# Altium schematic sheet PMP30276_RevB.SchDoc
size 431 x 279 mm; Date: Not shown in title block; ApprovedBy: Not shown in title block; CheckedBy: Not shown in title block; Author: Not shown in title block; CompanyName: Not shown in title block; Engineer: Not shown in title block; Organization: Not shown in title block; Address1: Not shown in title block; Address2: Not shown in title block; Address3: Not shown in title block; Address4: Not shown in title block; DocumentNumber: 1; Revision: Use project parameter SCH_Rev; SheetNumber: 1; SheetTotal: 1; PageSetup: Record=PageOptions¦CenterHorizontal=True¦CenterVertical=True¦PrintScale=1.00¦XCorrection=1.00¦YCorrection=1.00¦PrintKind=0¦BorderSize=5000000¦LeftOffset=0¦BottomOffset=0¦Orientation=2¦PaperLength=1000¦PaperWidth=1000¦Scale=100¦PaperSource=15¦PrintQuality=600¦MediaType=1¦DitherType=10¦PaperKind=Letter¦PrintScaleMode=1
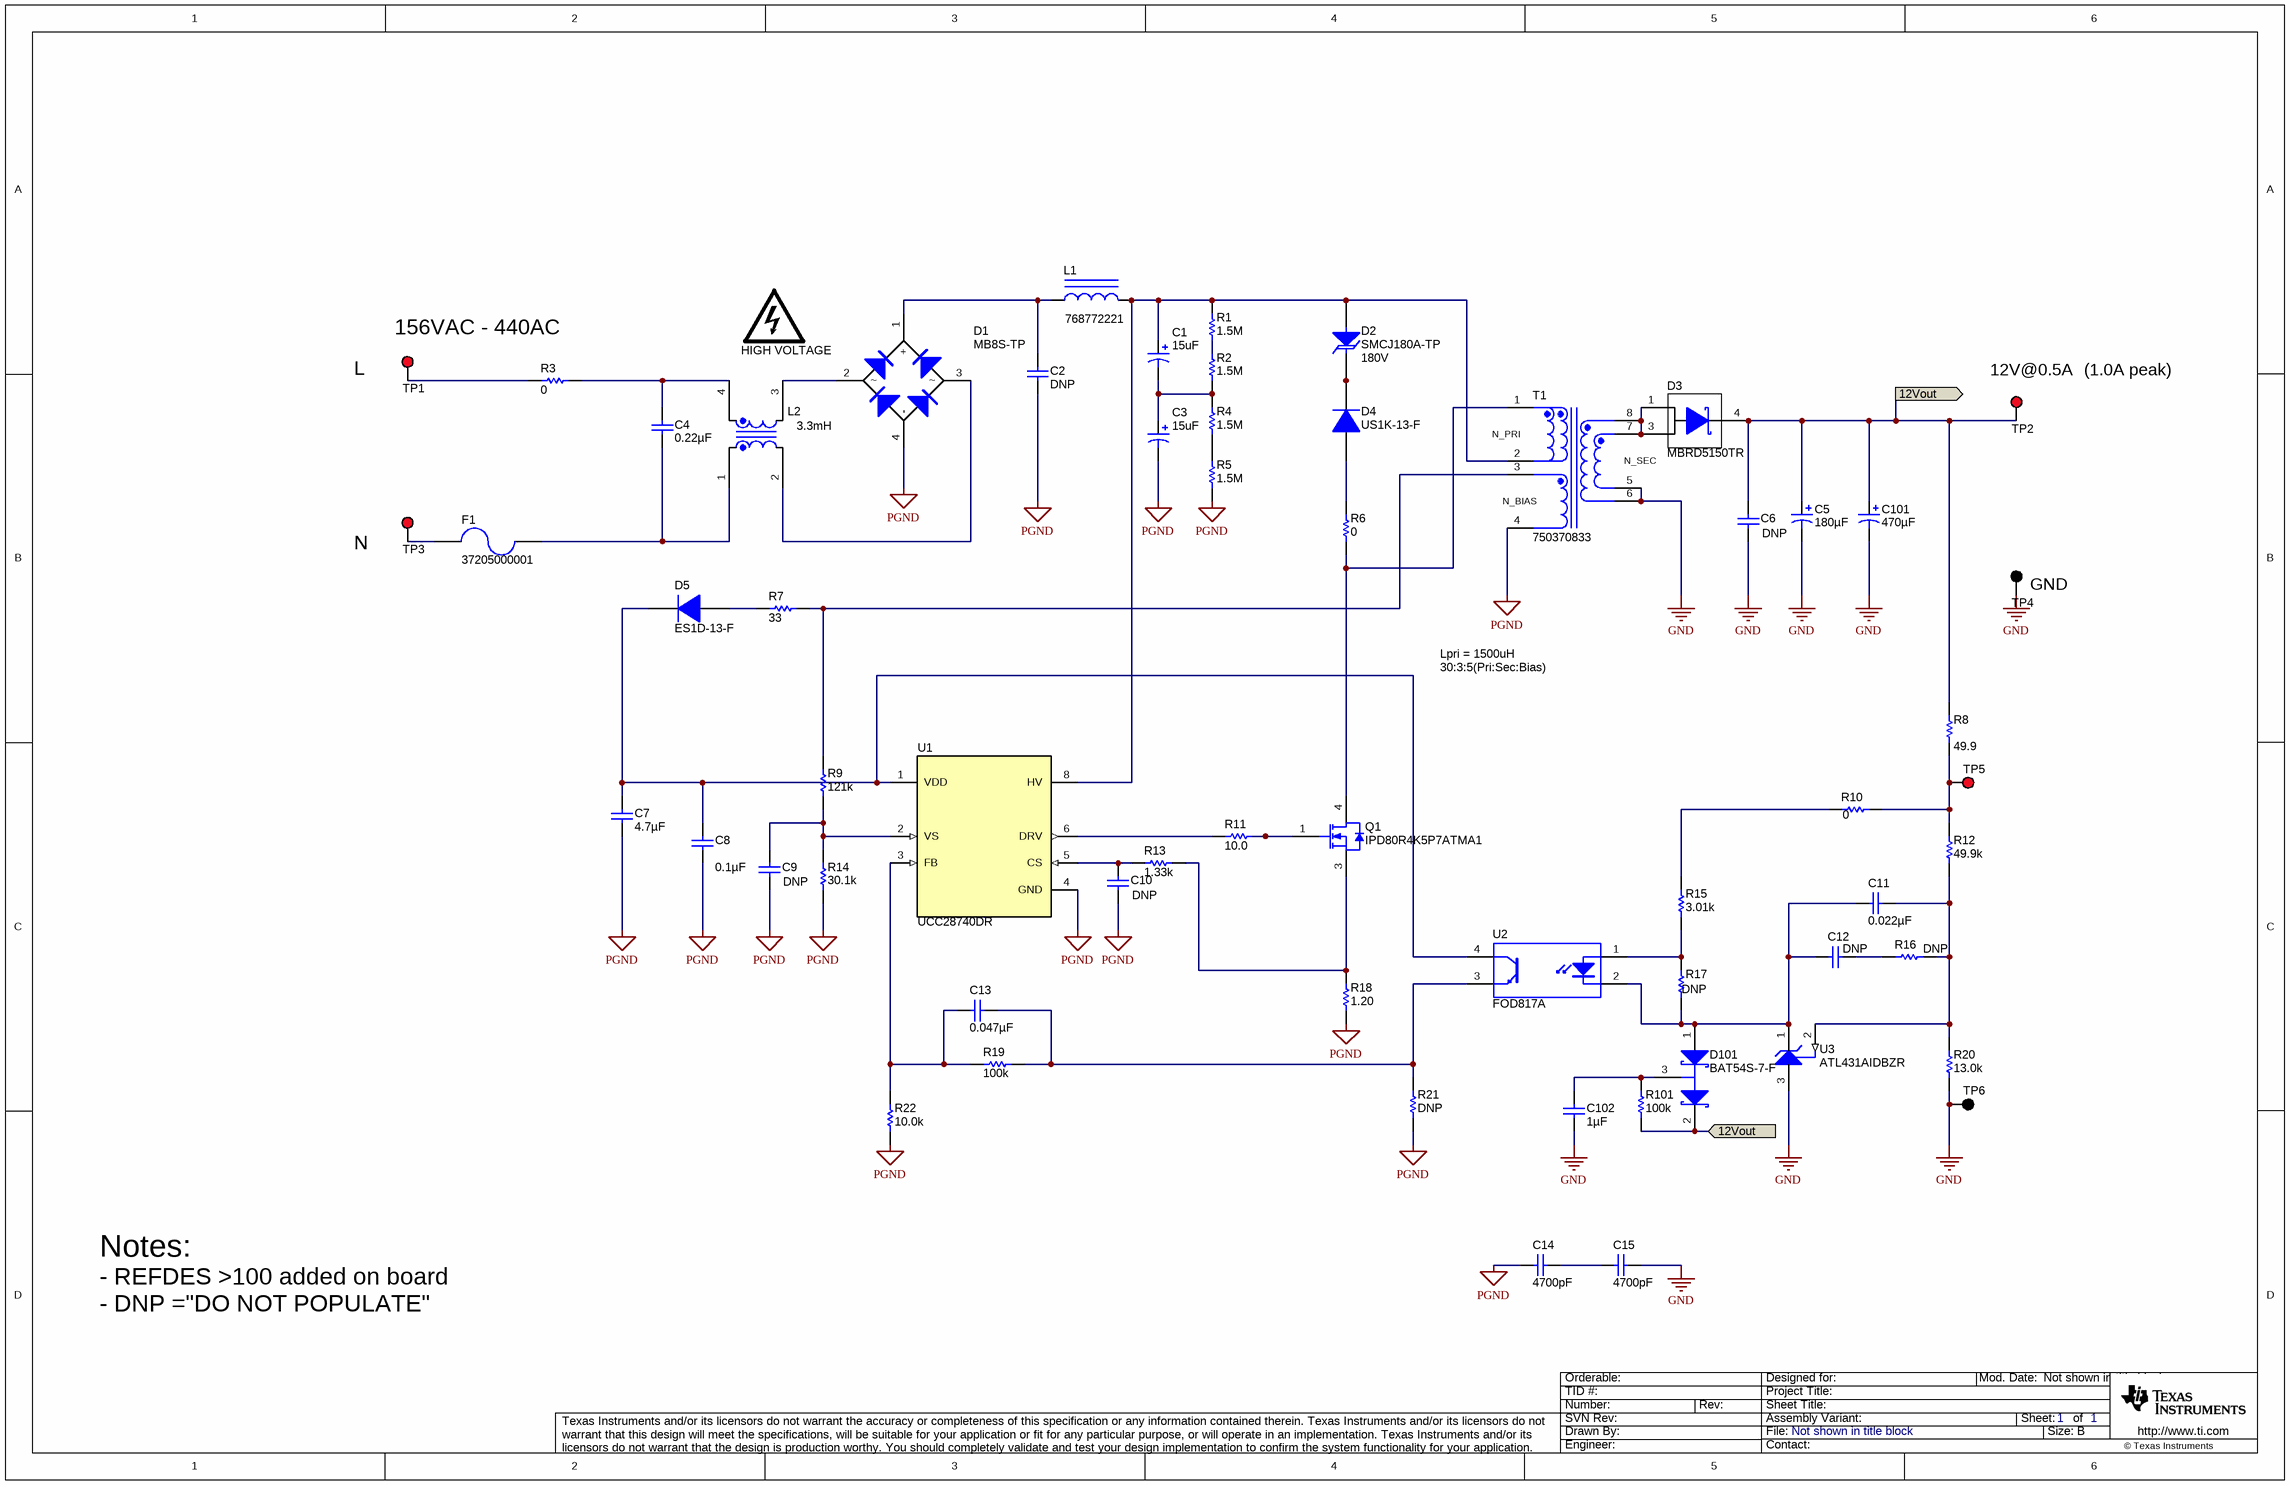
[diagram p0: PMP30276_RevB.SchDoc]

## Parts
C1  value 15uF  [CAPPR5-10x20]  (hidden comment: EEU-EE2V150)
C2  DNP  [B32913_2650x1050x1850]
C3  value 15uF  [CAPPR5-10x20]  (hidden comment: EEU-EE2V150)
C4  ValueDisplayed: 0.22µF  [B32913_2650x1050x1850]  (hidden comment: R474N322050A1K)
C5  ValueDisplayed: 180µF  [CAPSMT_62_F61]  (hidden comment: 16SVPF180M)
C6  value DNP  [1210]  (hidden comment: Used in BOM report)
C7  ValueDisplayed: 4.7µF  [1206_180]  (hidden comment: C3216X7R1H475K160AC)
C8  ValueDisplayed: 0.1µF  [0603]  (hidden comment: 06035C104KAT2A)
C9  value DNP  [0603_HV]  (hidden comment: Used in BOM report)
C10  value DNP  [0603]  (hidden comment: Used in BOM report)
C11  ValueDisplayed: 0.022µF  [0603]  (hidden comment: C0603C223K5RACTU)
C12  value DNP  [0805]  (hidden comment: Used in BOM report)
C13  ValueDisplayed: 0.047µF  [0603]  (hidden comment: C1608X7R1H473K080AA)
C14  ValueDisplayed: 4700pF  [KY_1000x500x1300]  (hidden comment: DE2E3KY472MB3BM02F)
C15  ValueDisplayed: 4700pF  [KY_1000x500x1300]  (hidden comment: DE2E3KY472MB3BM02F)
C101  ValueDisplayed: 470µF  [SM_RADIAL_10BMM]  (hidden comment: EEHZK1E471P)
C102  ValueDisplayed: 1µF  [0805_HV]  (hidden comment: GRM21BR71E105KA99L)
D1  MB8S-TP  [MBS-1]
D2  SMCJ180A-TP  value 180V  [SMC_265]
D3  MBRD5150TR  [DPAK]
D4  US1K-13-F  [SMA]
D5  ES1D-13-F  [SMA]
D101  BAT54S-7-F  [SOT-23]
F1  37205000001  [FUSE_372]
HIGH_VOLTAGE  DANGER HIGH VOLTAGE  [IEC_HighVoltage_Small]  (value not drawn)  (no BOM)
L1  768772221  [WE-TI_8095]
L2  value 3.3mH  [WE-CMB_Type_S]  (hidden comment: 744822233)
Q1  IPD80R4K5P7ATMA1  [DPAK]
R1  ValueDisplayed: 1.5M  [0805_HV]  (hidden comment: CRCW08051M50JNEA)
R2  ValueDisplayed: 1.5M  [0805_HV]  (hidden comment: CRCW08051M50JNEA)
R3  ValueDisplayed: 0  [1206]  (hidden comment: CRCW12060000Z0EA)
R4  ValueDisplayed: 1.5M  [0805_HV]  (hidden comment: CRCW08051M50JNEA)
R5  ValueDisplayed: 1.5M  [0805_HV]  (hidden comment: CRCW08051M50JNEA)
R6  ValueDisplayed: 0  [2512]  (hidden comment: CRCW25120000Z0EG)
R7  ValueDisplayed: 33  [0805_HV]  (hidden comment: CRCW080533R0JNEA)
R8  ValueDisplayed: 49.9  [0603]  (hidden comment: CRCW060349R9FKEA)
R9  ValueDisplayed: 121k  [0603]  (hidden comment: CRCW0603121KFKEA)
R10  ValueDisplayed: 0  [0603]  (hidden comment: CRCW06030000Z0EA)
R11  ValueDisplayed: 10.0  [0805_HV]  (hidden comment: RC0805FR-0710RL)
R12  ValueDisplayed: 49.9k  [0603]  (hidden comment: CRCW060349K9FKEA)
R13  ValueDisplayed: 1.33k  [0603]  (hidden comment: CRCW06031K33FKEA)
R14  ValueDisplayed: 30.1k  [0603]  (hidden comment: CRCW060330K1FKEA)
R15  ValueDisplayed: 3.01k  [0603]  (hidden comment: CRCW06033K01FKEA)
R16  value DNP  [0603]  (hidden comment: Used in BOM report)
R17  value DNP  [0603]  (hidden comment: Used in BOM report)
R18  ValueDisplayed: 1.20  [0805_HV]  (hidden comment: ERJ-6RQF1R2V)
R19  ValueDisplayed: 100k  [0603]  (hidden comment: CRCW0603100KFKEA)
R20  ValueDisplayed: 13.0k  [0603]  (hidden comment: CRCW060313K0FKEA)
R21  value DNP  [0603]  (hidden comment: Used in BOM report)
R22  ValueDisplayed: 10.0k  [0603]  (hidden comment: CRCW060310K0FKEA)
R101  ValueDisplayed: 100k  [0805_HV]  (hidden comment: CRCW0805100KFKEA)
T1  750370833  [Wurth_750370833]
TP1  5000  [Keystone5000]  (value not drawn)
TP2  5000  [Keystone5000]  (value not drawn)
TP3  5000  [Keystone5000]  (value not drawn)
TP4  5001  [Keystone5001]  (value not drawn)
TP5  5000  [Keystone5000]  (value not drawn)
TP6  5001  [Keystone5001]  (value not drawn)
U1  UCC28740DR  [D0007A_N]
U2  FOD817A  [DIP-4]
U3  ATL431AIDBZR  [DBZ0003A_N]

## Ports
12Vout (in), 12Vout (out)

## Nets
GND: C5.2(-) C6.2 C15.1 C101.2(-) C102.2 R20.1 T1.5 T1.6 TP4.1 TP6.1 U3.3(ANODE)
PGND: C2.2 C3.2(-) C7.2 C8.2 C9.2 C10.2 C14.2 D1.4(-) R5.1 R14.1 R18.1 R21.2 R22.1 T1.4 U1.4(GND)
12Vout: C5.1(+) C6.1 C101.1(+) D3.4(K) D101.2(K) R8.2 R101.1 TP2.1 ; port 12Vout
NetC1_1: C1.1(+) D2.2(A) L1.2 R1.2 T1.2 U1.8(HV)
NetC1_2: C1.2(-) C3.1(+) R2.1 R4.2
NetC2_1: C2.1 D1.1(+) L1.1
NetC4_1: C4.1 L2.4 R3.2
NetC4_2: C4.2 F1.1 L2.1
NetC7_1: C7.1 C8.1 D5.1(K) U1.1(VDD) U2.4(C)
NetC9_1: C9.1 R9.1 R14.2 U1.2(VS)
NetC10_1: C10.1 R13.1 U1.5(CS)
NetC11_1: C11.1 R12.1 R16.1 R20.2 U3.2(REF)
NetC11_2: C11.2 C12.1 D101.1(A) R17.1 U2.2(K) U3.1(CATHODE)
NetC12_2: C12.2 R16.2
NetC13_1: C13.1 R19.2 R21.1 U2.3(E)
NetC13_2: C13.2 R19.1 R22.2 U1.3(FB)
NetC14_1: C14.1 C15.2
NetC102_1: C102.1 D101.3(C) R101.2
NetD1_2: D1.2 L2.3
NetD1_3: D1.3 L2.2
NetD2_1: D2.1(K) D4.1(K)
NetD3_1: D3.1(A) D3.3(A) T1.7 T1.8
NetD4_2: D4.2(A) R6.2
NetD5_2: D5.2(A) R7.1
NetF1_2: F1.2 TP3.1
NetQ1_1: Q1.1(G) R11.2
NetQ1_3: Q1.3(S) R13.2 R18.2
NetQ1_4: Q1.4(D) R6.1 T1.1
NetR1_1: R1.1 R2.2
NetR3_1: R3.1 TP1.1
NetR4_1: R4.1 R5.2
NetR7_2: R7.2 R9.2 T1.3
NetR8_1: R8.1 R10.2 R12.2 TP5.1
NetR10_1: R10.1 R15.2
NetR11_1: R11.1 U1.6(DRV)
NetR15_1: R15.1 R17.2 U2.1(A)

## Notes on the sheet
- 156VAC - 440AC
- (near TP1) L
- (near T1) N_PRI
- (near TP2) 12V@0.5A
- (1.0A peak)
- (near T1) N_BIAS
- N_SEC
- (near TP3) N
- (near TP4) GND
- 30:3:5(Pri:Sec:Bias)
- Lpri = 1500uH
- Notes:
- - REFDES >100 added on board
- - DNP ="DO NOT POPULATE"

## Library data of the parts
C1 C3 = Capacitor_Polarized: CAP, [Technology], 15uF, 350V, +/-xx%, xxOhm ESR, [MountType]; Manufacturer: Used in BOM report; Polarized: Y; U/M: EA; Dielectric Material: Aluminium; Tolerance_%: 20%; Ripple Current: 480mA; Life (Hours): 8000Hour; Leakage Current: 325uA; Dissipation Factor: 0.2%; Lead Diameter: 0.6mm
C2 = B32913B5224K000: CAP, Film; Manufacturer: TDK; Polarized: N; CompType: Capacitor; U/M: EA; Cap_F: 0.00000022; Tolerance_%: 10; VDC_V: 1000; Value2: 440VAC; TaMin_C: -40; TaMax_C: 110; Cap_Case: 26.5x10.5x18.5mm; SizeAreaWB_mm2: 356.25; SizeArea_mm2: 278.25; SizeX_mm: 26.5; SizeY_mm: 10.5; SizeZ_mm: 18.5; AEC Category: Q200; Green_Lifecycle: Not Set; Green_REACh: Incomplete; Dielectric Material: PP; Voltage Rating (AC): 440V; Voltage Rating (DC): 1kV
C4 = B32913B5224K000: CAP, Film, 0.22 µF, 440VAC,+/- 10%, TH; Manufacturer: TDK; Polarized: N; CompType: Capacitor; Value: 0.22uF; U/M: EA; Cap_F: 0.00000022; Tolerance_%: 10; VDC_V: 1000; TaMin_C: -40; TaMax_C: 110; Cap_Case: 26.5x10.5x18.5mm; SizeAreaWB_mm2: 356.25; SizeArea_mm2: 278.25; SizeX_mm: 26.5; SizeY_mm: 10.5; SizeZ_mm: 18.5; AEC Category: Q200; Green_Lifecycle: Not Set; Green_REACh: Incomplete; Dielectric Material: PP; Voltage Rating (AC): 440V; Voltage Rating (DC): 1kV
C5 = 16SVPF180M: CAP, Aluminum Polymer, 180 µF, 16 V,+/- 20%, 0.022 ohm, F61 SMD; Manufacturer: Panasonic; Polarized: Y; CompType: Capacitor; Value: 180uF; U/M: EA; Cap_F: 0.00018; Tolerance_%: 20; VDC_V: 16; Value2: 16V; ESR_ohm: 0.022; IRMS_A: 3.3; TaMin_C: -55; TaMax_C: 105; SizeAreaWB_mm2: 73.96; SizeArea_mm2: 43.56; SizeX_mm: 6.6; SizeZ_mm: 5.8; AEC Category: Q200; Green_Lifecycle: Not Set; Green_REACh: Incomplete
C6 C9 C10 C12 = Capacitor: CAP, CERM, xxxF, xxV, [TempCo], xx%, [PackageReference]; Polarized: N; U/M: EA
C7 = C3216X7R1H475K160AC: CAP, CERM, 4.7 µF, 50 V,+/- 10%, X7R, 1206; Manufacturer: TDK; Polarized: N; CompType: Capacitor; Value: 4.7uF; U/M: EA; Cap_F: 0.0000047; Tolerance_%: 10; ESR_ohm: 0.003158; Value1: 0.003158 ohm; VDC_V: 50; Value2: 50V; IRMS_A: 4.08379; TaMin_C: -55; TaMax_C: 125; Cap_Case: 1206; SizeArea_mm2: 5.12; SizeAreaWB_mm2: 10.92; SizeX_mm: 3.2; SizeY_mm: 1.6; SizeZ_mm: 1.8; AEC Category: Q200
C8 = 06035C104KAT2A: CAP, CERM, 0.1 µF, 50 V, +/- 10%, X7R, 0603; Manufacturer: AVX; Polarized: N; CompType: Capacitor; Value: 0.1uF; U/M: EA; Cap_F: 0.0000001; Tolerance_%: 10; Value1: Unknown; VDC_V: 50; Value2: 50V; TaMin_C: -55; TaMax_C: 125; SizeArea_mm2: 1.28; SizeAreaWB_mm2: 4.68; SizeX_mm: 1.6; SizeY_mm: 0.8; SizeZ_mm: 1; AEC Category: Q200
C11 = C0603C223K5RACTU: CAP, CERM, 0.022 µF, 50 V,+/- 10%, X7R, 0603; Manufacturer: Kemet; Polarized: N; CompType: Capacitor; Value: 0.022uF; U/M: EA; Cap_F: 0.000000022; Tolerance_%: 10; VDC_V: 50; Value2: 50V; TaMin_C: -55; TaMax_C: 125; SizeArea_mm2: 1.28; SizeAreaWB_mm2: 4.68; SizeX_mm: 1.6; SizeY_mm: 0.8; SizeZ_mm: 1; AEC Category: Q200; Green_Lifecycle: Active; Green_REACh: Passed
C13 = C1608X7R1H473K080AA: CAP, CERM, 0.047 µF, 50 V,+/- 10%, X7R, 0603; Manufacturer: TDK; Polarized: N; CompType: Capacitor; Value: 0.047uF; U/M: EA; Cap_F: 0.000000047; Tolerance_%: 10; ESR_ohm: 0.049007; Value1: 0.049007 ohm; VDC_V: 50; Value2: 50V; IRMS_A: 0.767528; TaMin_C: -55; TaMax_C: 125; SizeArea_mm2: 1.28; SizeAreaWB_mm2: 4.68; SizeX_mm: 1.6; SizeY_mm: 0.8; SizeZ_mm: 1; AEC Category: Q200; Green_Lifecycle: NRND; Green_REACh: Passed
C14 C15 = DE2E3KY472MB3BM02F: CAP, CERM, 4700 pF, X1 250 VAC/Y2 300 VAC, +/- 20%, E, 10x5x13mm; Manufacturer: MuRata; Polarized: N; CompType: Capacitor; Value: 4700pF; U/M: EA; Cap_F: 0.0000000047; Tolerance_%: 20; TaMin_C: -40; TaMax_C: 125; SizeArea_mm2: 50; SizeAreaWB_mm2: 84; SizeX_mm: 10; SizeY_mm: 5; SizeZ_mm: 13; AEC Category: Q200; AC_Safety: X1Y2; VAC_X: 250; VAC_Y: 300
C101 = EEHZC1E331P: CAP, Polymer Hybrid, 470 µF, 25 V,; Manufacturer: Panasonic; Polarized: Y; CompType: Capacitor; Value: 470uF; U/M: EA; Cap_F: 0.00033; Tolerance_%: 20; VDC_V: 25; Value2: 25V; IRMS_A: 2; TaMin_C: -55; TaMax_C: 125; SizeAreaWB_mm2: 159.9; SizeArea_mm2: 113.3; SizeX_mm: 11; SizeY_mm: 10.3; SizeZ_mm: 10.2; AEC Category: Q200
C102 = GRM21BR71E105KA99L: CAP, CERM, 1 µF, 25 V,+/- 10%, X7R, 0805; Manufacturer: MuRata; Polarized: N; CompType: Capacitor; Value: 1uF; U/M: EA; Cap_F: 0.000001; Tolerance_%: 10; VDC_V: 25; Value2: 25V; TaMin_C: -55; TaMax_C: 125; Cap_Case: 0805; SizeArea_mm2: 2.5; SizeAreaWB_mm2: 6.75; SizeX_mm: 2; SizeY_mm: 1.25; SizeZ_mm: 1.45; AEC Category: Q200; Green_Lifecycle: Active; Green_REACh: Passed
D1 = MB8S-TP: Diode, Switching-Bridge, 800 V, 0.5 A, TO269AA; Manufacturer: Micro Commercial Components; U/M: EA; Vf_V: 1; Value: 800V; Value1: 0.5A; Value2: 1V; Io_A: 0.5; Vr_V: 800; TJmax_C: 150; SizeAreaWB_mm2: 58.725; SizeArea_mm2: 31.825; SizeX_mm: 6.7; SizeY_mm: 4.75; SizeZ_mm: 2.7; AEC Category: Q101; Green_Lifecycle: Not Set; Green_REACh: Incomplete
D2 = SMCJ160A-TP: Diode, TVS, Uni, 180 V,; Manufacturer: Micro Commercial Components; U/M: EA; Vr_V: 160; Value1: W; SizeAreaWB_mm2: 78.5757; SizeArea_mm2: 46.8857; SizeX_mm: 7.94; SizeY_mm: 5.905; SizeZ_mm: 2.62; AEC Category: Q101; AEC Qualified: N
D3 = DIODE_SCHOTTKY_A13C4: Diode, Schottky, 150V, 5A, [PackageReference]; Manufacturer: SMC Diode Solutions; U/M: EA
D4 = US1K-13-F: Diode, Fast Rectifier, 800 V, 1 A, SMA; Manufacturer: Diodes Inc.; U/M: EA; Vf_V: 1.7; Value: 800V; Value1: 1A; Value2: 1.7V; Io_A: 1; Vr_V: 800; TJmax_C: 150; SizeAreaWB_mm2: 37.3428; SizeArea_mm2: 16.3228; SizeX_mm: 5.59; SizeY_mm: 2.92; SizeZ_mm: 2.87; AEC Category: Q101; Green_Lifecycle: Not Set; Green_REACh: Incomplete
D5 = ES1D-13-F: Diode, Ultrafast, 200 V, 1 A, SMA; Manufacturer: Diodes Inc.; U/M: EA; Vf_V: 0.92; Value: 200V; Value1: 1A; Value2: 0.92V; Io_A: 1; Vr_V: 200; TJmax_C: 150; RJC_CperW: 25; SizeAreaWB_mm2: 37.3428; SizeArea_mm2: 16.3228; SizeX_mm: 5.59; SizeY_mm: 2.92; SizeZ_mm: 2.87; AEC Category: Q101; Green_Lifecycle: Active; Green_REACh: Passed
D101 = BAT54S-7-F: Diode, Schottky, 30 V, 0.2 A, SOT-23; Manufacturer: Diodes Inc.; U/M: EA; Vf_V: 0.65; Value: 30V; Value1: 0.2A; Value2: 0.65V; Io_A: 0.2; Vr_V: 30; TJmax_C: 125; SizeAreaWB_mm2: 14; SizeArea_mm2: 7.5; SizeX_mm: 2.5; SizeY_mm: 3; SizeZ_mm: 1.1; AEC Category: Q101; Green_Lifecycle: Active; Green_REACh: Passed
F1 = 37205000001: Fuse, 0.5 A, 250VAC/VDC, TH; Manufacturer: Littelfuse; VDC_V: 250; Irating_A: 0.5
HIGH_VOLTAGE = IEC_HighVoltage: IEC 61010-1 High Voltage Warning; SymbolCreator: a0412235
L1 = 768772681: Inductor, Unshielded Drum Core, Powdered Iron, 220 µH,; Manufacturer: Wurth Elektronik; Value: 220uH; ValueDisplayed: 220µH; Ind_H: 680.0E-6; Imax_A: 0.76; Isat: 0.76A @ 10% inductance drop; DCR_ohm: 1.68; Value1: 1.68 ohm; Value2: 0.76A; SizeAreaWB_mm2: 96.04; SizeArea_mm2: 60.84; SizeX_mm: 7.8; SizeZ_mm: 10; AEC Category: Q200; Green_Lifecycle: Active; Green_REACh: Passed; Tolerance_%: 10%; Current Rating: 900mA; Saturation Current: 1.3A; Self Resonant Frequency: 3.7MHz; Test Frequency: 100KHz
L2 = 744822110: Coupled inductor, 3300uH, 1.5 A; Manufacturer: Wurth Elektronik; SymbolCreator: a0412235; Ind_H: 10.0E-3; DCR_ohm: 0.36; AEC Category: Q200
Q1 = IPD80R1K0CEBTMA1: MOSFET, N-CH, 800 V, DPAK; Manufacturer: Infineon Technologies; Alternate Manufacturer: None; U/M: EA; ChType: N; Value: 800V; VdsMax_V: 800; Value1: ? ohm; QgTyp_nC: 31; Vgs_V: 20; IdsMax_A: 5.7; SizeAreaWB_mm2: 101.7114; SizeArea_mm2: 64.8114; SizeX_mm: 9.91; SizeY_mm: 6.54; SizeZ_mm: 2.29; AEC Category: Q101; Green_Lifecycle: Not Set; Green_REACh: Incomplete; Continuous Drain Current (ID): 1.5A; Max Power Dissipation: 13W
R1 R2 R4 R5 = CRCW08051M50JNEA: RES, 1.5 M, 5%, 0.125 W, 0805; Manufacturer: Vishay-Dale; CompType: Resistor; Value: 1.5Meg; Res_ohm: 1500000; Value_Code: 1M50; Tolerance_%: 5; Power_W: 0.125; Value2: 0.125W; VDC_V: 150; TempCo: 200 ppm/C; SizeArea_mm2: 2.5; SizeX_mm: 2; SizeY_mm: 1.25; SizeZ_mm: 1.45; EIA_Code: E24; U/M: EA; AEC Category: Q200; Green_Lifecycle: Active; Green_REACh: Passed
R3 = CRCW12060000Z0EA: RES, 0, 5%, 0.25 W, 1206; Manufacturer: Vishay-Dale; CompType: Resistor; Value: 0; Value_Code: 0000; Tolerance_%: 5; Power_W: 0.25; Value2: 0.25W; VDC_V: 200; TempCo: 200 ppm/C; SizeArea_mm2: 5.12; SizeX_mm: 3.2; SizeY_mm: 1.6; SizeZ_mm: 1.35; EIA_Code: E24; U/M: EA; AEC Category: Q200; Green_Lifecycle: Active; Green_REACh: Passed
R6 = CRCW25120000Z0EG: RES, 0, 5%, 1 W, AEC-Q200 Grade 0, 2512; Manufacturer: Vishay-Dale; CompType: Resistor; Value: 0; Value_Code: 0000; Tolerance_%: 5; Power_W: 1; Value2: 1W; TempCo: ppm/C; SizeArea_mm2: 20.16; SizeX_mm: 6.3; SizeY_mm: 3.2; SizeZ_mm: 0.71; EIA_Code: E24; U/M: EA; AEC Category: Q200; AEC Qualified: Y
R7 = CRCW080533R0JNEA: RES, 33, 5%, 0.125 W, 0805; Manufacturer: Vishay-Dale; CompType: Resistor; Value: 33; Value_Code: 33R0; Tolerance_%: 5; Power_W: 0.125; Value2: 0.125W; VDC_V: 150; TempCo: 200 ppm/C; SizeArea_mm2: 2.5; SizeX_mm: 2; SizeY_mm: 1.25; SizeZ_mm: 1.45; EIA_Code: E24; U/M: EA; AEC Category: Q200
R8 = CRCW060349R9FKEA: RES, 49.9, 1%, 0.1 W, 0603; Manufacturer: Vishay-Dale; CompType: Resistor; Value: 49.9; Value_Code: 49R9; Tolerance_%: 1; Power_W: 0.1; Value2: 0.1W; VDC_V: 75; TempCo: 100 ppm/C; SizeArea_mm2: 1.28; SizeX_mm: 1.6; SizeY_mm: 0.8; EIA_Code: E96; U/M: EA; AEC Category: Q200
R9 = CRCW0603121KFKEA: RES, 121 k, 1%, 0.1 W, 0603; Manufacturer: Vishay-Dale; CompType: Resistor; Value: 121k; Res_ohm: 121000; Tolerance_%: 1; Power_W: 0.1; Value2: 0.1W; VDC_V: 75; TempCo: 100 ppm/C; SizeArea_mm2: 1.28; SizeX_mm: 1.6; SizeY_mm: 0.8; EIA_Code: E96; U/M: EA; AEC Category: Q200; Green_Lifecycle: Active; Green_REACh: Passed
R10 = CRCW06030000Z0EA: RES, 0, 5%, 0.1 W, 0603; Manufacturer: Vishay-Dale; CompType: Resistor; Value: 0; Value_Code: 0000; Tolerance_%: 5; Power_W: 0.1; Value2: 0.1W; VDC_V: 75; TempCo: 200 ppm/C; SizeArea_mm2: 1.28; SizeX_mm: 1.6; SizeY_mm: 0.8; SizeZ_mm: 1; EIA_Code: E24; U/M: EA; AEC Category: Q200
R11 = RC0805FR-0710RL: RES, 10.0, 1%, 0.125 W, 0805; Manufacturer: Yageo America; CompType: Resistor; Value: 10.0; Res_ohm: 10; Value_Code: 10R0; Tolerance_%: 1; Power_W: 0.125; Value2: 0.125W; VDC_V: 150; TempCo: 200 ppm/C; SizeArea_mm2: 2.5; SizeX_mm: 2; SizeY_mm: 1.25; SizeZ_mm: 1.45; EIA_Code: E96; U/M: EA; AEC Category: Q200; Green_Lifecycle: Active; Green_REACh: Passed
R12 = CRCW060349K9FKEA: RES, 49.9 k, 1%, 0.1 W, 0603; Manufacturer: Vishay-Dale; CompType: Resistor; Value: 49.9k; Res_ohm: 49900; Value_Code: 49k9; Tolerance_%: 1; Power_W: 0.1; Value2: 0.1W; VDC_V: 75; TempCo: 100 ppm/C; SizeArea_mm2: 1.28; SizeX_mm: 1.6; SizeY_mm: 0.8; EIA_Code: E96; U/M: EA; AEC Category: Q200; Green_Lifecycle: Active; Green_REACh: Passed
R13 = CRCW06031K33FKEA: RES, 1.33 k, 1%, 0.1 W, 0603; Manufacturer: Vishay-Dale; CompType: Resistor; Value: 1.33k; Res_ohm: 1330; Value_Code: 1k33; Tolerance_%: 1; Power_W: 0.1; Value2: 0.1W; VDC_V: 75; TempCo: 100 ppm/C; SizeArea_mm2: 1.28; SizeX_mm: 1.6; SizeY_mm: 0.8; EIA_Code: E96; U/M: EA; AEC Category: Q200
R14 = CRCW060330K1FKEA: RES, 30.1 k, 1%, 0.1 W, 0603; Manufacturer: Vishay-Dale; CompType: Resistor; Value: 30.1k; Res_ohm: 30100; Value_Code: 30k1; Tolerance_%: 1; Power_W: 0.1; Value2: 0.1W; VDC_V: 75; TempCo: 100 ppm/C; SizeArea_mm2: 1.28; SizeX_mm: 1.6; SizeY_mm: 0.8; EIA_Code: E96; U/M: EA; AEC Category: Q200; Green_Lifecycle: Active; Green_REACh: Passed
R15 = CRCW06033K01FKEA: RES, 3.01 k, 1%, 0.1 W, 0603; Manufacturer: Vishay-Dale; CompType: Resistor; Value: 3.01k; Res_ohm: 3010; Value_Code: 3k01; Tolerance_%: 1; Power_W: 0.1; Value2: 0.1W; VDC_V: 75; TempCo: 100 ppm/C; SizeArea_mm2: 1.28; SizeX_mm: 1.6; SizeY_mm: 0.8; EIA_Code: E96; U/M: EA; AEC Category: Q200; Green_Lifecycle: Active; Green_REACh: Passed
R16 R17 R21 = Resistor: RES, xxx ohm, x%, xW, [PackageReference]; U/M: EA
R18 = ERJ-6RQF1R2V: RES, 1.20, 1%, 0.125 W, 0805; Manufacturer: Panasonic; CompType: Resistor; Value: 1.20; Res_ohm: 1.2; Value_Code: 1R20; Tolerance_%: 1; Power_W: 0.125; Value2: 0.125W; TempCo: 200 ppm/C; SizeArea_mm2: 2.5; SizeX_mm: 2; SizeY_mm: 1.25; SizeZ_mm: 1.45; U/M: EA; AEC Category: Q200
R19 = CRCW0603100KFKEA: RES, 100 k, 1%, 0.1 W, 0603; Manufacturer: Vishay-Dale; CompType: Resistor; Value: 100k; Res_ohm: 100000; Tolerance_%: 1; Power_W: 0.1; Value2: 0.1W; VDC_V: 75; TempCo: 100 ppm/C; SizeArea_mm2: 1.28; SizeX_mm: 1.6; SizeY_mm: 0.8; EIA_Code: E96; U/M: EA; AEC Category: Q200; Green_Lifecycle: Active; Green_REACh: Passed
R20 = CRCW060313K0FKEA: RES, 13.0 k, 1%, 0.1 W, 0603; Manufacturer: Vishay-Dale; CompType: Resistor; Value: 13.0k; Res_ohm: 13000; Value_Code: 13k0; Tolerance_%: 1; Power_W: 0.1; Value2: 0.1W; VDC_V: 75; TempCo: 100 ppm/C; SizeArea_mm2: 1.28; SizeX_mm: 1.6; SizeY_mm: 0.8; EIA_Code: E96; U/M: EA; AEC Category: Q200; Green_Lifecycle: Active; Green_REACh: Passed
R22 = CRCW060310K0FKEA: RES, 10.0 k, 1%, 0.1 W, 0603; Manufacturer: Vishay-Dale; CompType: Resistor; Value: 10.0k; Res_ohm: 10000; Value_Code: 10k0; Tolerance_%: 1; Power_W: 0.1; Value2: 0.1W; VDC_V: 75; TempCo: 100 ppm/C; SizeArea_mm2: 1.28; SizeX_mm: 1.6; SizeY_mm: 0.8; EIA_Code: E96; U/M: EA; AEC Category: Q200; Green_Lifecycle: Active; Green_REACh: Passed
R101 = CRCW0805100KFKEA: RES, 100 k, 1%, 0.125 W, 0805; Manufacturer: Vishay-Dale; CompType: Resistor; Value: 100k; Res_ohm: 100000; Tolerance_%: 1; Power_W: 0.125; Value2: 0.125W; VDC_V: 150; TempCo: 100 ppm/C; SizeArea_mm2: 2.5; SizeX_mm: 2; SizeY_mm: 1.25; SizeZ_mm: 1.45; EIA_Code: E96; U/M: EA; AEC Category: Q200; Green_Lifecycle: Active; Green_REACh: Passed
T1 = CMP-0077094-1: Transformer, 1500 uH, TH; Manufacturer: Wurth Elektronik; SizeAreaWB_mm2: 529.4072; SizeArea_mm2: 441.3672; AEC Qualified: N; Lp: 1500.0; AEC Category: Q200; Value: 1.5mH; SizeZ_mm: 15.88; SizeY_mm: 21.24; Ns1toNp: 0.09794; LeakageInd_H: 22µH; Rsec1_ohm: 0.037; DCR_ohm: 3.7; SizeX_mm: 20.78
TP1-TP3 TP5 = 5000: Test Point, Miniature, Red, TH; Manufacturer: Keystone; CompType: Test Point Loop; ContactFinish: Silver
TP4 TP6 = 5001: Test Point, Miniature, Black, TH; Manufacturer: Keystone; CompType: Test Point Loop; ContactFinish: Silver
U1 = UCC28740DR: Constant-Voltage, Constant-Current Flyback Controller Using Opto-Coupler Feedback, D0007A; Manufacturer: Texas Instruments; SymbolCreator: a0412235; SizeArea_mm2: 29.4; SizeAreaWB_mm2: 55.2; SizeX_mm: 6; SizeY_mm: 4.9; SizeZ_mm: 1.75; CompType: IC; U/M: EA
U2 = FOD817A: Optocoupler, 5 kV, 80-160% CTR, TH; Manufacturer: Fairchild Semiconductor; CTR (Min): 80%; CTR (Max): 160%; Voltage_Isolation_Vrms: 5000V
U3 = ATL431AIDBZR: 2.5V Low Iq Adjustable Precision Shunt Regulator, DBZ0003A (SOT-23-3); Manufacturer: Texas Instruments; SymbolCreator: a0412235; SizeArea_mm2: 7.5; SizeAreaWB_mm2: 14; SizeX_mm: 2.5; SizeY_mm: 3; SizeZ_mm: 1.12; CompType: IC; U/M: EA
